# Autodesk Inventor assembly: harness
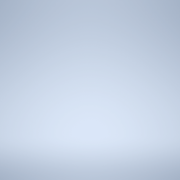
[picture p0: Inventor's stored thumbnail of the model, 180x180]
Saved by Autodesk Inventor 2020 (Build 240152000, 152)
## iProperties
Shininess: 64.0
Length Units: 11272
Angle Units: 11279
Time Units: 11290
Mass Units: 11286
Length Display Precision: 3
Angle Display Precision: 2
Compacted: True
HarnessSettings: <HarnessSettings><Defaults><Segments><Diameter value="0.200 in" fromwires="True"/><Offset value="0.100 in"/><ColorStyle value="Blue"/><BendRadius value="19" fro
Part Number: harness
Document SubType Name: Assembly
Created: 2002-07
Material: Všeobecné
Density: 0.0
Volumn: 0.0
Area: 0.0
PropertySet Name: Model Information
Control State: 0
Master: False
Checked Out: False
HarnessSettings: <HarnessSettings><Defaults><Segments><Diameter value="0.200 in" fromwires="True"/><Offset value="0.100 in"/><ColorStyle value="Modrá – nástěnná malba – lesklá"/
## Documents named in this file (1)
- C:\Users\Smoke\Desktop\csy\harness.iam
